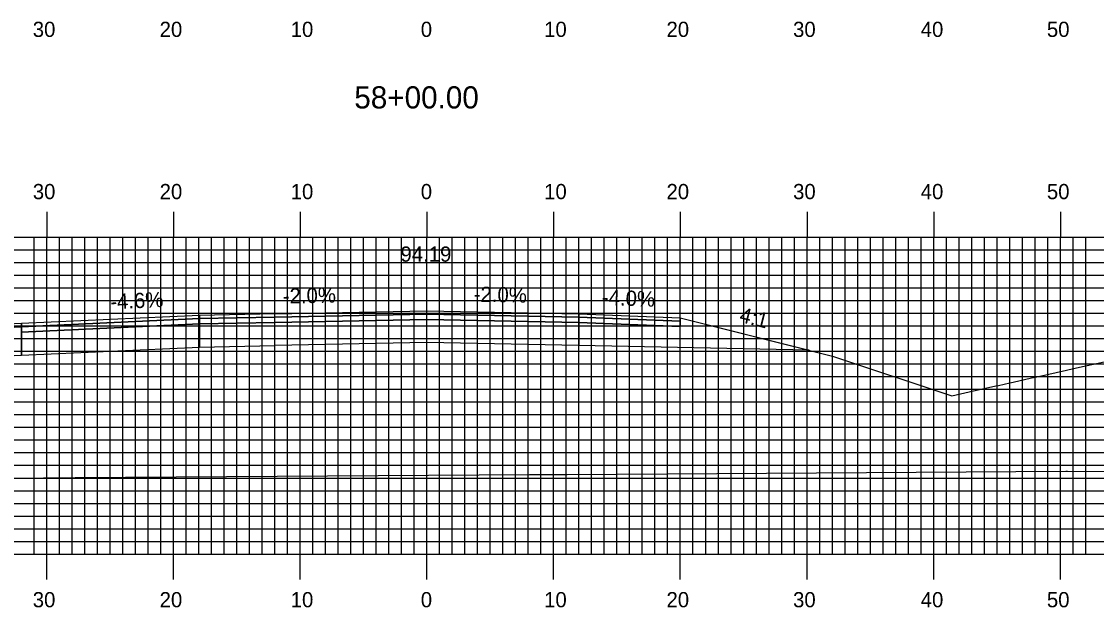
# Model space of a CAD drawing. Extents: x 1757069 to 1757412, y 442591 to 442811.
# Drawn here: x 1757202.6 to 1757287.4, y 442699.4 to 442745.7 of the extents above; entities that cross this region are included whole.
import ezdxf

# ---------------------------------------------------------------- set-up
doc = ezdxf.new("R2010")
doc.units = 0
for name, color, linetype in [('ANNOTATION', 7, 'Continuous'), ('D_Roadway_Centerline', 7, 'Continuous'), ('D_Roadway_Centerline_Text', 7, 'Continuous'), ('D_Roadway_Edge_Shoulder', 7, 'Continuous'), ('D_Roadway_Edge_TW', 7, 'Continuous'), ('D_Roadway_Pavement', 7, 'Continuous'), ('D_Roadway_SlopeLines', 7, 'Continuous'), ('D_Roadway_SubGrade', 7, 'Continuous'), ('H_V ANNOTATION', 7, 'Continuous'), ('MAJOR', 7, 'Continuous'), ('MINOR', 7, 'Continuous'), ('S_Roadway_Centerline', 7, 'Continuous')]:
    doc.layers.add(name, color=color, linetype=linetype)

msp = doc.modelspace()

# ---------------------------------------------------------------- linework, layer by layer
at = {"layer": 'D_Roadway_Centerline'}
msp.add_lwpolyline([(1757276.026, 442716.147), (1757277.395, 442716.455), (1757279.508, 442716.929), (1757279.717, 442716.976), (1757280.602, 442717.175), (1757280.872, 442717.236), (1757282.312, 442717.558), (1757282.613, 442717.626), (1757285.078, 442718.177), (1757285.171, 442718.198), (1757286.343, 442718.46), (1757287.806, 442718.787), (1757289.745, 442719.22), (1757290.497, 442719.388), (1757290.578, 442719.406), (1757290.728, 442719.439), (1757292.015, 442719.726), (1757293.153, 442719.979), (1757295.066, 442720.405), (1757295.773, 442720.562), (1757298.223, 442721.106)], dxfattribs=at)
at = {"layer": 'D_Roadway_Edge_Shoulder'}
for points in [[(1757246.596, 442722.61), (1757254.596, 442722.29), (1757254.596, 442722.04), (1757246.596, 442722.36)], [(1757202.61, 442721.848), (1757185.198, 442721.051), (1757185.198, 442720.801), (1757202.61, 442721.598)]]:
    msp.add_lwpolyline(points, close=True, dxfattribs=at)
at = {"layer": 'D_Roadway_Edge_TW'}
for points in [[(1757222.596, 442722.61), (1757216.663, 442722.492), (1757216.663, 442722.242), (1757222.596, 442722.36)], [(1757222.596, 442722.36), (1757222.596, 442722.61), (1757234.596, 442722.85), (1757246.596, 442722.61), (1757246.596, 442722.36), (1757234.596, 442722.6)], [(1757216.663, 442722.492), (1757202.61, 442721.848), (1757202.61, 442721.598), (1757216.663, 442722.242)]]:
    msp.add_lwpolyline(points, close=True, dxfattribs=at)
msp.add_lwpolyline([(1757216.663, 442722.492), (1757216.663, 442722.242)], dxfattribs=at)
at = {"layer": 'D_Roadway_Pavement'}
for points in [[(1757216.663, 442722.242), (1757202.61, 442721.598), (1757202.61, 442721.182), (1757216.663, 442721.825)], [(1757222.596, 442722.36), (1757216.663, 442722.242), (1757216.663, 442721.825), (1757222.596, 442721.944)], [(1757222.596, 442721.944), (1757222.596, 442722.36), (1757234.596, 442722.6), (1757246.596, 442722.36), (1757246.596, 442721.944), (1757234.596, 442722.184)], [(1757246.596, 442722.36), (1757254.596, 442722.04), (1757254.596, 442721.624), (1757246.596, 442721.944)]]:
    msp.add_lwpolyline(points, close=True, dxfattribs=at)
for points in [[(1757216.663, 442722.242), (1757216.663, 442721.825)], [(1757216.663, 442722.242), (1757216.663, 442721.825)], [(1757202.61, 442721.598), (1757202.61, 442721.182)]]:
    msp.add_lwpolyline(points, dxfattribs=at)
at = {"layer": 'D_Roadway_SlopeLines'}
msp.add_lwpolyline([(1757254.596, 442722.29), (1757266.596, 442719.29), (1757276.026, 442716.147)], dxfattribs=at)
at = {"layer": 'D_Roadway_SubGrade'}
for points in [[(1757216.663, 442721.825), (1757202.61, 442721.182), (1757202.61, 442719.348), (1757216.663, 442719.992)], [(1757222.596, 442721.944), (1757216.663, 442721.825), (1757216.663, 442719.992), (1757222.596, 442720.11)], [(1757222.596, 442720.11), (1757222.596, 442721.944), (1757234.596, 442722.184), (1757246.596, 442721.944), (1757246.596, 442720.11), (1757234.596, 442720.35)], [(1757246.596, 442721.944), (1757254.596, 442721.624), (1757254.596, 442722.04), (1757254.596, 442722.29), (1757264.77, 442719.747), (1757246.596, 442720.11)], [(1757202.61, 442721.182), (1757202.61, 442721.598), (1757185.198, 442720.801), (1757185.198, 442721.051), (1757173.662, 442718.023), (1757202.61, 442719.348)]]:
    msp.add_lwpolyline(points, close=True, dxfattribs=at)
msp.add_lwpolyline([(1757216.663, 442721.825), (1757216.663, 442719.992)], dxfattribs=at)
at = {"layer": 'MAJOR'}
for p, q in [((1757204.596, 442730.669), (1757204.596, 442728.665)), ((1757214.596, 442730.669), (1757214.596, 442728.665)), ((1757224.596, 442730.669), (1757224.596, 442728.665)), ((1757234.596, 442730.669), (1757234.596, 442728.665)), ((1757244.596, 442730.669), (1757244.596, 442728.665)), ((1757254.596, 442730.669), (1757254.596, 442728.665)), ((1757264.596, 442730.669), (1757264.596, 442728.665)), ((1757274.596, 442730.669), (1757274.596, 442728.665)), ((1757284.596, 442730.669), (1757284.596, 442728.665)), ((1757094.596, 442728.665), (1757374.596, 442728.665)), ((1757094.596, 442728.665), (1757374.596, 442728.665)), ((1757204.596, 442703.665), (1757204.596, 442728.665)), ((1757214.596, 442703.665), (1757214.596, 442728.665)), ((1757224.596, 442703.665), (1757224.596, 442728.665)), ((1757234.596, 442703.665), (1757234.596, 442728.665)), ((1757244.596, 442703.665), (1757244.596, 442728.665)), ((1757254.596, 442703.665), (1757254.596, 442728.665)), ((1757264.596, 442703.665), (1757264.596, 442728.665)), ((1757274.596, 442703.665), (1757274.596, 442728.665)), ((1757284.596, 442703.665), (1757284.596, 442728.665)), ((1757094.596, 442723.665), (1757374.596, 442723.665)), ((1757094.596, 442718.665), (1757374.596, 442718.665)), ((1757094.596, 442713.665), (1757374.596, 442713.665)), ((1757094.596, 442708.665), (1757374.596, 442708.665)), ((1757094.596, 442703.665), (1757374.596, 442703.665)), ((1757094.596, 442703.665), (1757374.596, 442703.665)), ((1757204.596, 442701.661), (1757204.596, 442703.665)), ((1757214.596, 442701.661), (1757214.596, 442703.665)), ((1757224.596, 442701.661), (1757224.596, 442703.665)), ((1757234.596, 442701.661), (1757234.596, 442703.665)), ((1757244.596, 442701.661), (1757244.596, 442703.665)), ((1757254.596, 442701.661), (1757254.596, 442703.665)), ((1757264.596, 442701.661), (1757264.596, 442703.665)), ((1757274.596, 442701.661), (1757274.596, 442703.665)), ((1757284.596, 442701.661), (1757284.596, 442703.665))]:
    msp.add_line(p, q, dxfattribs=at)
at = {"layer": 'MINOR'}
for p, q in [((1757203.596, 442703.665), (1757203.596, 442728.665)), ((1757205.596, 442703.665), (1757205.596, 442728.665)), ((1757206.596, 442703.665), (1757206.596, 442728.665)), ((1757207.596, 442703.665), (1757207.596, 442728.665)), ((1757208.596, 442703.665), (1757208.596, 442728.665)), ((1757209.596, 442703.665), (1757209.596, 442728.665)), ((1757210.596, 442703.665), (1757210.596, 442728.665)), ((1757211.596, 442703.665), (1757211.596, 442728.665)), ((1757212.596, 442703.665), (1757212.596, 442728.665)), ((1757213.596, 442703.665), (1757213.596, 442728.665)), ((1757215.596, 442703.665), (1757215.596, 442728.665)), ((1757216.596, 442703.665), (1757216.596, 442728.665)), ((1757217.596, 442703.665), (1757217.596, 442728.665)), ((1757218.596, 442703.665), (1757218.596, 442728.665)), ((1757219.596, 442703.665), (1757219.596, 442728.665)), ((1757220.596, 442703.665), (1757220.596, 442728.665)), ((1757221.596, 442703.665), (1757221.596, 442728.665)), ((1757222.596, 442703.665), (1757222.596, 442728.665)), ((1757223.596, 442703.665), (1757223.596, 442728.665)), ((1757225.596, 442703.665), (1757225.596, 442728.665)), ((1757226.596, 442703.665), (1757226.596, 442728.665)), ((1757227.596, 442703.665), (1757227.596, 442728.665)), ((1757228.596, 442703.665), (1757228.596, 442728.665)), ((1757229.596, 442703.665), (1757229.596, 442728.665)), ((1757230.596, 442703.665), (1757230.596, 442728.665)), ((1757231.596, 442703.665), (1757231.596, 442728.665)), ((1757232.596, 442703.665), (1757232.596, 442728.665)), ((1757233.596, 442703.665), (1757233.596, 442728.665)), ((1757235.596, 442703.665), (1757235.596, 442728.665)), ((1757236.596, 442703.665), (1757236.596, 442728.665)), ((1757237.596, 442703.665), (1757237.596, 442728.665)), ((1757238.596, 442703.665), (1757238.596, 442728.665)), ((1757239.596, 442703.665), (1757239.596, 442728.665)), ((1757240.596, 442703.665), (1757240.596, 442728.665)), ((1757241.596, 442703.665), (1757241.596, 442728.665)), ((1757242.596, 442703.665), (1757242.596, 442728.665)), ((1757243.596, 442703.665), (1757243.596, 442728.665)), ((1757245.596, 442703.665), (1757245.596, 442728.665)), ((1757246.596, 442703.665), (1757246.596, 442728.665)), ((1757247.596, 442703.665), (1757247.596, 442728.665)), ((1757248.596, 442703.665), (1757248.596, 442728.665)), ((1757249.596, 442703.665), (1757249.596, 442728.665)), ((1757250.596, 442703.665), (1757250.596, 442728.665)), ((1757251.596, 442703.665), (1757251.596, 442728.665)), ((1757252.596, 442703.665), (1757252.596, 442728.665)), ((1757253.596, 442703.665), (1757253.596, 442728.665)), ((1757255.596, 442703.665), (1757255.596, 442728.665)), ((1757256.596, 442703.665), (1757256.596, 442728.665)), ((1757257.596, 442703.665), (1757257.596, 442728.665)), ((1757258.596, 442703.665), (1757258.596, 442728.665)), ((1757259.596, 442703.665), (1757259.596, 442728.665)), ((1757260.596, 442703.665), (1757260.596, 442728.665)), ((1757261.596, 442703.665), (1757261.596, 442728.665)), ((1757262.596, 442703.665), (1757262.596, 442728.665)), ((1757263.596, 442703.665), (1757263.596, 442728.665)), ((1757265.596, 442703.665), (1757265.596, 442728.665)), ((1757266.596, 442703.665), (1757266.596, 442728.665)), ((1757267.596, 442703.665), (1757267.596, 442728.665)), ((1757268.596, 442703.665), (1757268.596, 442728.665)), ((1757269.596, 442703.665), (1757269.596, 442728.665)), ((1757270.596, 442703.665), (1757270.596, 442728.665)), ((1757271.596, 442703.665), (1757271.596, 442728.665)), ((1757272.596, 442703.665), (1757272.596, 442728.665)), ((1757273.596, 442703.665), (1757273.596, 442728.665)), ((1757275.596, 442703.665), (1757275.596, 442728.665)), ((1757276.596, 442703.665), (1757276.596, 442728.665)), ((1757277.596, 442703.665), (1757277.596, 442728.665)), ((1757278.596, 442703.665), (1757278.596, 442728.665)), ((1757279.596, 442703.665), (1757279.596, 442728.665)), ((1757280.596, 442703.665), (1757280.596, 442728.665)), ((1757281.596, 442703.665), (1757281.596, 442728.665)), ((1757282.596, 442703.665), (1757282.596, 442728.665)), ((1757283.596, 442703.665), (1757283.596, 442728.665)), ((1757285.596, 442703.665), (1757285.596, 442728.665)), ((1757286.596, 442703.665), (1757286.596, 442728.665)), ((1757094.596, 442727.665), (1757374.596, 442727.665)), ((1757094.596, 442726.665), (1757374.596, 442726.665)), ((1757094.596, 442725.665), (1757374.596, 442725.665)), ((1757094.596, 442724.665), (1757374.596, 442724.665)), ((1757094.596, 442722.665), (1757374.596, 442722.665)), ((1757094.596, 442721.665), (1757374.596, 442721.665)), ((1757094.596, 442720.665), (1757374.596, 442720.665)), ((1757094.596, 442719.665), (1757374.596, 442719.665)), ((1757094.596, 442717.665), (1757374.596, 442717.665)), ((1757094.596, 442716.665), (1757374.596, 442716.665)), ((1757094.596, 442715.665), (1757374.596, 442715.665)), ((1757094.596, 442714.665), (1757374.596, 442714.665)), ((1757094.596, 442712.665), (1757374.596, 442712.665)), ((1757094.596, 442711.665), (1757374.596, 442711.665)), ((1757094.596, 442710.665), (1757374.596, 442710.665)), ((1757094.596, 442709.665), (1757374.596, 442709.665)), ((1757094.596, 442707.665), (1757374.596, 442707.665)), ((1757094.596, 442706.665), (1757374.596, 442706.665)), ((1757094.596, 442705.665), (1757374.596, 442705.665)), ((1757094.596, 442704.665), (1757374.596, 442704.665))]:
    msp.add_line(p, q, dxfattribs=at)
at = {"layer": 'S_Roadway_Centerline'}
msp.add_lwpolyline([(1757094.596, 442709.181), (1757117.334, 442709.26), (1757140.809, 442709.082), (1757149.644, 442709.105), (1757165.923, 442709.273), (1757181.503, 442709.374), (1757191.75, 442709.552), (1757206.827, 442709.715), (1757242.693, 442709.941), (1757244.489, 442709.954), (1757245.674, 442709.953), (1757285.017, 442710.208), (1757285.149, 442710.21), (1757316.078, 442710.104), (1757319.992, 442710.085), (1757358.793, 442710.052), (1757374.596, 442710.005)], dxfattribs=at)

# ---------------------------------------------------------------- texts
at = {"layer": 'ANNOTATION'}
for s, rotation, p in [('-4.6%', 2.62123, (1757209.633, 442722.972)), ('-2.0%', 1.14576, (1757223.236, 442723.423)), ('-2.0%', 358.85424, (1757238.282, 442723.577)), ('-4.0%', 357.70939, (1757248.388, 442723.34)), ('4:1', 345.96376, (1757259.189, 442722.004))]:
    msp.add_text(s, height=1.2, rotation=rotation, dxfattribs=at).set_placement(p)
at = {"layer": 'D_Roadway_Centerline'}
for s, p in [('C', (1757234.591, 442722.85)), ('L', (1757234.596, 442722.843))]:
    msp.add_text(s, height=0.0146, dxfattribs=at).set_placement(p)
at = {"layer": 'D_Roadway_Centerline_Text'}
msp.add_text('94.19', height=1.2, dxfattribs=at).set_placement((1757232.509, 442726.733))
at = {"layer": 'H_V ANNOTATION'}
for s, height, p in [('30', 1.2, (1757203.493, 442744.465)), ('20', 1.2, (1757213.504, 442744.465)), ('10', 1.2, (1757223.847, 442744.465)), ('0', 1.2, (1757234.114, 442744.465)), ('10', 1.2, (1757243.847, 442744.465)), ('20', 1.2, (1757253.504, 442744.465)), ('30', 1.2, (1757263.493, 442744.465)), ('40', 1.2, (1757273.568, 442744.465)), ('50', 1.2, (1757283.525, 442744.465)), ('58+00.00', 1.75, (1757228.868, 442738.821)), ('30', 1.2, (1757203.493, 442731.665)), ('20', 1.2, (1757213.504, 442731.665)), ('10', 1.2, (1757223.847, 442731.665)), ('0', 1.2, (1757234.114, 442731.665)), ('10', 1.2, (1757243.847, 442731.665)), ('20', 1.2, (1757253.504, 442731.665)), ('30', 1.2, (1757263.493, 442731.665)), ('40', 1.2, (1757273.568, 442731.665)), ('50', 1.2, (1757283.525, 442731.665)), ('30', 1.2, (1757203.493, 442699.465)), ('20', 1.2, (1757213.504, 442699.465)), ('10', 1.2, (1757223.847, 442699.465)), ('0', 1.2, (1757234.114, 442699.465)), ('10', 1.2, (1757243.847, 442699.465)), ('20', 1.2, (1757253.504, 442699.465)), ('30', 1.2, (1757263.493, 442699.465)), ('40', 1.2, (1757273.568, 442699.465)), ('50', 1.2, (1757283.525, 442699.465))]:
    msp.add_text(s, height=height, dxfattribs=at).set_placement(p)

doc.saveas('drawing.dxf')
